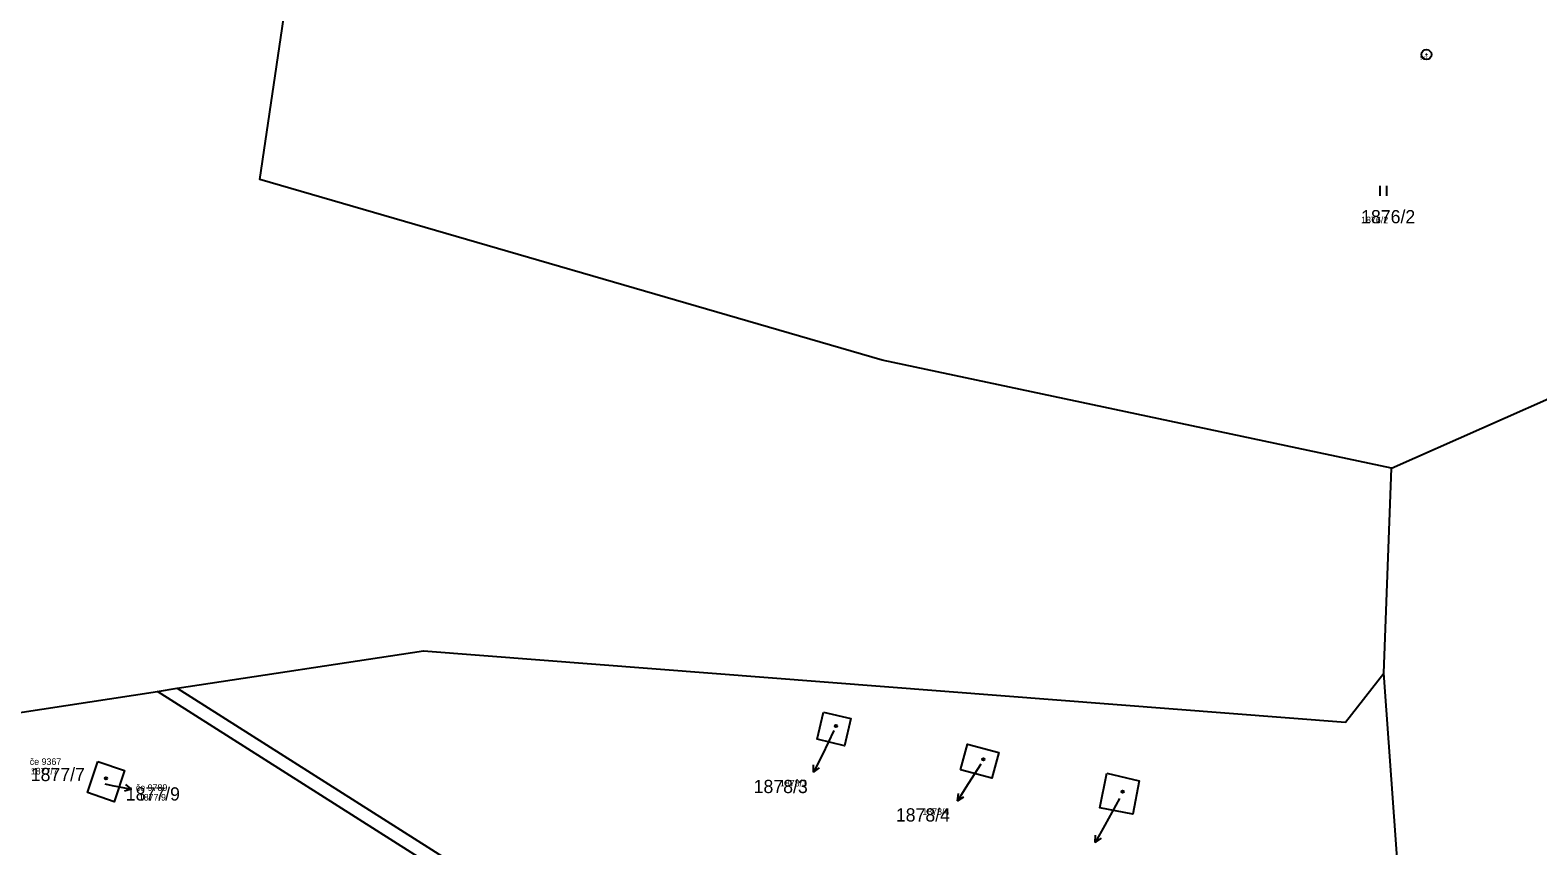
# Model space of a CAD drawing. Extents: x -763628 to -761565, y -976033 to -973833.
# Drawn here: x -763228.1 to -763000.2, y -975042.1 to -974918.8 of the extents above; entities that cross this region are included whole.
import ezdxf

# ---------------------------------------------------------------- set-up
doc = ezdxf.new("R2010")
doc.units = 0
for name, color, linetype in [('KN_cisla parcel 1000', 7, 'Continuous'), ('KN_cisla parcel 500', 7, 'Continuous'), ('KN_cisla parcel znacky', 7, 'Continuous'), ('KN_cisla popisna 500', 7, 'Continuous'), ('KN_hranice parcel', 7, 'Continuous'), ('KN_znacky bodu BP', 7, 'Continuous'), ('KN_znacky budov', 7, 'Continuous'), ('KN_znacky kultur', 7, 'Continuous')]:
    doc.layers.add(name, color=color, linetype=linetype)

msp = doc.modelspace()

# ---------------------------------------------------------------- linework, layer by layer
at = {"layer": 'KN_cisla parcel znacky'}
for p, q in [((-763106.59, -975024.7), (-763108.34, -975028.3)), ((-763108.34, -975028.3), (-763109.66, -975031)), ((-763109.66, -975031), (-763109.67, -975029.88)), ((-763109.66, -975031), (-763108.77, -975030.32)), ((-763084.39, -975029.77), (-763086.3, -975032.77)), ((-763216.85, -975032.77), (-763215.73, -975032.98)), ((-763215.73, -975032.98), (-763212.78, -975033.55)), ((-763212.78, -975033.55), (-763213.86, -975033.85)), ((-763212.78, -975033.55), (-763213.67, -975032.87)), ((-763086.3, -975032.77), (-763087.89, -975035.32)), ((-763087.89, -975035.32), (-763087.78, -975034.2)), ((-763087.89, -975035.32), (-763086.94, -975034.73)), ((-763063.41, -975034.99), (-763065.63, -975038.98)), ((-763065.63, -975038.98), (-763067.09, -975041.61)), ((-763067.09, -975041.61), (-763067.04, -975040.49)), ((-763067.09, -975041.61), (-763066.16, -975040.97))]:
    msp.add_line(p, q, dxfattribs=at)
at = {"layer": 'KN_hranice parcel'}
for p, q in [((-763022.28, -974985.03), (-762977.1, -974965.05)), ((-763023.43, -975016.01), (-763022.28, -974985.03)), ((-763208.89, -975018.78), (-763205.88, -975018.32))]:
    msp.add_line(p, q, dxfattribs=at)
for points in [[(-763022.28, -974985.03), (-763099.32, -974968.74), (-763193.4, -974941.43), (-763184.48, -974881.09)], [(-763205.88, -975018.32), (-763168.63, -975012.63), (-763029.23, -975023.44), (-763023.43, -975016.01)], [(-763014.38, -975097.95), (-763018.02, -975091.5), (-763023.43, -975016.01)], [(-763252.23, -975037.94), (-763247.53, -975024.69), (-763208.89, -975018.78)], [(-763009.92, -975145.39), (-763134.76, -975065.78), (-763208.89, -975018.78)], [(-763205.88, -975018.32), (-763133.69, -975064.09), (-763003.03, -975146.67)], [(-763108.15, -975021.9), (-763104.02, -975022.9), (-763105.01, -975026.99), (-763109.14, -975025.99), (-763108.15, -975021.9)], [(-763087.44, -975030.64), (-763086.42, -975026.77), (-763081.68, -975028.02), (-763082.7, -975031.89), (-763087.44, -975030.64)], [(-763217.88, -975029.37), (-763213.85, -975030.76), (-763215.43, -975035.46), (-763219.45, -975034.08), (-763217.88, -975029.37)], [(-763065.32, -975031.13), (-763060.42, -975032.29), (-763061.42, -975037.36), (-763066.39, -975036.37), (-763065.32, -975031.13)]]:
    msp.add_lwpolyline(points, dxfattribs=at)
at = {"layer": 'KN_znacky bodu BP'}
for radius in [0.75, 0.03]:
    msp.add_circle((-763017, -974922.53), radius, dxfattribs=at)
at = {"layer": 'KN_znacky budov'}
for centre in [(-763106.29, -975024), (-763083.98, -975029.05), (-763216.67, -975031.92), (-763062.94, -975033.96)]:
    msp.add_circle(centre, 0.175, dxfattribs=at)
at = {"layer": 'KN_znacky kultur'}
for p, q in [((-763024.01, -974943.89), (-763024.01, -974942.39)), ((-763023.01, -974943.89), (-763023.01, -974942.39))]:
    msp.add_line(p, q, dxfattribs=at)

# ---------------------------------------------------------------- texts
at = {"layer": 'KN_cisla parcel 1000'}
for s, p in [('1876/2', (-763026.88, -974948.04)), ('1877/7', (-763228.03, -975032.34)), ('1877/9', (-763213.66, -975035.28)), ('1878/3', (-763118.73, -975034.15)), ('1878/4', (-763097.23, -975038.45))]:
    msp.add_text(s, height=2, dxfattribs=at).set_placement(p)
at = {"layer": 'KN_cisla parcel 500'}
for s, p in [('1876/2', (-763026.88, -974948.04)), ('1877/7', (-763228.03, -975031.34)), ('1878/3', (-763114.76, -975033.15)), ('1877/9', (-763211.69, -975035.28)), ('1878/4', (-763093.23, -975037.45))]:
    msp.add_text(s, height=1, dxfattribs=at).set_placement(p)
at = {"layer": 'KN_cisla popisna 500'}
for s, p in [('če 9367', (-763228.18, -975029.9)), ('če 9789', (-763212.14, -975033.82))]:
    msp.add_text(s, height=1, dxfattribs=at).set_placement(p)
at = {"layer": 'KN_znacky bodu BP'}
msp.add_text('547', height=0.5, dxfattribs=at).set_placement((-763017.97, -974923.28))

doc.saveas('drawing.dxf')
